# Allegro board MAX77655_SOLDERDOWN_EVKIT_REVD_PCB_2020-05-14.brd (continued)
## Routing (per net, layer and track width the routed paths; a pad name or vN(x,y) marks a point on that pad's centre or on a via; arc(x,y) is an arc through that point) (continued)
IN: length 89.5
  TOP w0.254: C5.2 30.85,23.66 v1(30.83,23.63)
  TOP w0.381: v1(1.71,64.93) SW2.1 2.85,63.75 3.67,62.94 R8.1 ; R37.1 8.74,46.1 8.72,46.08 2.48,46.08 2.44,46.12 v1(1.77,46.12)
  INTERNAL3 w0.254: v1(30.83,23.63) 28.74,23.63 24.9,27.47 6.6,27.47 5.31,28.76 5.31,28.95 IN_SNS.1
  INTERNAL3 w0.762: v1(1.71,64.93) 1.71,63.62 1.77,63.56 v1(1.77,46.12) 1.77,40.27 ; J5.1 1.96,40.46 1.77,40.27 ; IN.1 4.06,26.43 1.77,28.72 1.77,40.27
ISET_SBB0: length 12.6
  INTERNAL3 w0.254: v1(48.35,45.77) 48.35,46.52 48.35,46.53 v1(48.35,49.6)
  BOTTOM w0.254: U205.D2 42.98,46.42 43.64,45.76 47.73,45.76 47.74,45.77 v1(48.35,45.77) ; v1(48.35,49.6) 48.96,49.6 48.97,49.62 R203.1
ISET_SBB1: length 15.7
  INTERNAL3 w0.254: v1(46.25,36.93) 46.25,45.79 46.25,45.8 v1(46.25,46.41)
  BOTTOM w0.254: v1(46.25,46.41) 45.64,46.41 45.49,46.55 U205.D1 ; R224.1 48.91,37.19 48.65,36.93 v1(46.25,36.93)
ISET_SBB2: length 31.1
  INTERNAL3 w0.254: v1(46.87,23.23) 46.87,23.89 46.86,23.91 46.86,46.4 46.87,46.42 v1(46.87,47.03)
  BOTTOM w0.254: v1(46.87,23.23) 46.87,24.17 48.07,25.36 R237.1 ; v1(46.87,47.03) 46.23,47.03 46.2,47.06 U205.C1
ISET_SBB3: length 38.6
  INTERNAL3 w0.152: v1(44.2,47.72) 43.64,47.72 43.51,47.58 43.51,47.58 v2(43.15,47.23)
  INTERNAL3 w0.254: v1(47.6,47.71) v1(47.6,15.79)
  BOTTOM w0.152: U205.C2 42.98,47.06 v2(43.15,47.23)
  BOTTOM w0.254: v1(47.6,47.71) 46.72,47.71 46.71,47.72 v1(44.2,47.72) ; v1(47.6,15.79) R250.1
J3-5: length 20
  TOP w0.254: Q1.3 10.45,61.41 9.82,62.04 R8.2 7.43,62.04 v1(7.42,62.03)
  TOP w0.381: Q2.3 v1(7.42,65.72)
  INTERNAL3 w0.254: v1(7.42,65.72) 7.42,65.72 v1(7.42,62.03) 7.42,60.62 5.92,59.12 J3.5
LXB: length 2.2
  TOP w0.254: U1.C3 33.14,25.65 v2(32.99,25.49) ; U1.C3 v2(33.31,25.5) ; U1.C3 33,25.81 v2(33,25.82) ; U1.C3 33.31,25.8 33.31,25.8 33.32,25.81 v2(33.32,25.81)
  TOP w0.381: R34.1 34.8,22.06 v1(34.64,22.22)
  BOTTOM w0.152: 33.36,25.5 v2(33.31,25.5)
  BOTTOM w0.254: v2(32.99,25.49) 33.31,25.49 v2(33.31,25.5)
  BOTTOM w0.381: C4.2 33.71,25.46
  vias: v1(34.64,21.63)
NEN: length 119.5
  TOP w0.152: U1.C2 32.46,25.85 v2(32.46,25.86)
  TOP w0.203: v1(29.67,28.26) 25.66,32.27 v1(9.08,32.27)
  INTERNAL3 w0.203: v2(32.46,25.86) 32.07,25.86 v1(29.67,28.26)
  INTERNAL3 w0.254: J2.2 49.93,71.48 49.89,71.44 v1(49.89,69.64) ; v1(9.08,32.27) 9.08,32.88 9.1,32.89 v1(9.1,44.74) v1(9.1,68.77)
  BOTTOM w0.254: v1(49.89,69.64) 42.9,69.64 42.01,68.75 9.72,68.75 9.71,68.77 v1(9.1,68.77)
  BOTTOM w0.381: v1(9.1,44.74) 7.24,44.74 J3.2 J3.4 J3.6
NEN_EXT: length 9.7
  TOP w0.381: NEN_EXT.1 13.7,72.73 14.67,71.77 14.67,67.2 16.18,65.7 R33.1 16.19,64.91 R32.2
NEN_FTDI: length 38.1
  TOP w0.254: R31.1 11.13,63.12 11.13,63.12 v1(10.52,63.12)
  INTERNAL3 w0.254: v1(13.9,36.01) 13.9,40.03 11.38,42.55 11.38,62.26 v1(10.52,63.12)
  BOTTOM w0.254: U5.4 14.51,36.02 14.51,36.01 v1(13.9,36.01)
NIRQ: length 102.9
  TOP w0.152: U1.B2 32.49,26.32 v2(32.48,26.32)
  TOP w0.203: v1(29.56,29.25) 25.98,32.83 16.67,32.83 16.64,32.86 v1(16.06,32.86)
  TOP w0.254: NIRQ.1 15.38,39.28 15.39,39.29 v1(16.06,39.29) ; v1(16.67,65.97) v1(52.45,65.97)
  INTERNAL3 w0.152: v2(32.48,26.32) 32.48,26.33
  INTERNAL3 w0.203: v1(29.56,29.25) 32.18,26.63 32.19,26.63 32.48,26.33
  INTERNAL3 w0.254: v1(16.67,65.97) 16.67,61.65 16.06,61.04 v1(16.06,39.29) v1(16.06,32.86) ; J2.3 52.47,71.48 52.45,71.46 v1(52.45,65.97)
  BOTTOM w0.203: v1(16.06,32.86) 16.6,32.32
  BOTTOM w0.254: R27.2 R5.2 16.6,32.32
NIRQ_FTDI: length 2.2
  BOTTOM w0.254: U2.29 27.43,49.62 R19.1
RST#: length 2.5
  BOTTOM w0.254: R14.2 23.12,60.01 23.12,59.25 22.77,58.9 U2.14
SBB0: length 103.2
  TOP w0.203: v1(33.35,27.53) 33.45,27.63 33.45,27.96
  INTERNAL3 w0.203: B0_SNS.1 66.25,8.09 47.73,8.09 45.74,10.08 45.74,23.67 40.09,29.31 34.7,29.31 33.35,27.96 v1(33.35,27.53)
  INTERNAL3 w0.508: v1(33.58,30.68) 33.54,30.72 33.54,34.84 38.33,39.64 J4.4
  BOTTOM w0.508: B0_S.1 B0_SNS.1
  vias: v1(33.3,30.28)
SBB1: length 54.4
  TOP w0.203: U1.A4 33.85,26.84 33.85,27.02 34.46,27.63 34.46,27.66 v1(34.58,27.77) 34.7,27.89 35,27.89 35.05,27.93
  INTERNAL3 w0.203: v1(34.58,27.77) 34.99,28.18 37.26,28.18 37.56,28.49 39.04,28.49 44.56,22.98 44.56,9.31 46.81,7.05 61,7.05 B1_SNS.1
  BOTTOM w0.508: B1_S.1 B1_SNS.1
  vias: v1(38.3,27.83) v1(38.74,27.98)
SBB2: length 44.1
  INTERNAL3 w0.203: v1(34.6,26.64) 35.01,26.22 36.24,26.22 38.3,24.16 40.18,24.16 43.25,21.09 43.25,19.2 43.25,19.2 43.25,8.99 46.24,6 55.77,6 57.83,3.94 57.83,3.3 B2_SNS.1
  BOTTOM w0.508: B2_S.1 B2_SNS.1
  vias: v1(38.25,26.61) v1(38.68,26.33)
SBB3: length 36.6
  INTERNAL3 w0.203: v1(34.61,25.36) 35.19,25.36 37.51,23.04 39.26,23.04 42.13,20.18 42.13,8.25 45.41,4.97 49.91,4.97 B3_SNS.1
  BOTTOM w0.508: B3_S.1 B3_SNS.1
  vias: v1(38.34,25.52) v1(38.71,25.19)
SCL: length 96.6
  TOP w0.203: v1(26.51,33.04) 30.46,29.09 30.46,27.47 31.78,26.15 U1.B1
  TOP w0.254: J2.4 53.23,70.96 v1(44.74,70.96) ; SCL.1 11.57,34.42 12.96,34.42 13.14,34.25 25.31,34.25 v1(26.51,33.04)
  INTERNAL3 w0.254: v1(44.74,33.04) 44.74,47.38 44.75,47.39 44.75,47.77 44.74,47.78 v1(44.74,70.96)
  BOTTOM w0.203: R29.2 25.78,32.31 v1(26.51,33.04)
  BOTTOM w0.254: v1(26.51,33.04) v1(44.74,33.04)
SCL_FTDI: length 95.3
  TOP w0.254: v1(44.09,64.44) 44.09,64.29 43.68,63.89 v1(24.57,63.89)
  INTERNAL3 w0.203: v1(24.57,39.08) v1(24.57,57.68)
  INTERNAL3 w0.254: v1(24.57,63.89) 24.57,58.29 v1(24.57,57.68) ; v1(44.09,68.76) 44.09,68.08 44.09,68.08 v1(44.09,64.44) 44.09,63.83 44.11,63.81 44.11,55.03 39.67,50.58 39.67,50.4 v1(39.24,49.97)
  BOTTOM w0.203: v1(24.57,39.08) R22.2 24.01,38.15 23.48,37.62 U5.10 ; v1(24.57,57.68) 23.77,57.68 U2.16
  BOTTOM w0.254: v1(39.24,49.97) 39.05,49.97 38.75,49.66 R306.1 ; v1(44.09,68.76) 62,68.76 65.04,65.71 R304.1
  BOTTOM w0.381: R53.2 v1(44.09,64.44)
SDA: length 95.4
  TOP w0.203: U1.C1 31.55,25.65 v1(25.49,31.71) 19.8,31.71 19.76,31.67
  TOP w0.254: J2.5 55.15,70.33 46.13,70.33 v1(46.13,70.33) ; v1(19.77,31.7) 19.76,31.68 19.76,31.67 19.75,31.66 13.23,31.66 11.41,29.84 11.49,29.84 SDA.1
  INTERNAL3 w0.254: v1(45.53,32.99) 45.53,52.77 46.13,53.37 v1(46.13,70.33)
  BOTTOM w0.203: R30.2 19.77,32.28 19.77,31.82 19.77,31.82 v1(19.77,31.7)
  BOTTOM w0.254: v1(25.49,31.71) 26.1,31.71 26.75,32.36 44.9,32.36 v1(45.53,32.99)
SDA_FTDI: length 93.4
  TOP w0.254: 37.37,64.44 37.38,64.43 v1(37.38,64.42) ; 37.37,64.44 v1(42.84,64.44) ; 37.37,64.44 v1(25.83,64.44)
  INTERNAL3 w0.203: v1(25.82,56.05) v1(25.82,40.32)
  INTERNAL3 w0.254: v1(25.82,56.05) 25.82,56.66 25.83,56.67 v1(25.83,64.44) ; v1(42.84,64.44) 42.84,67.28 42.84,67.28 v1(42.84,67.95) ; v1(37.38,48.36) v1(37.38,64.42)
  BOTTOM w0.203: v1(25.82,40.32) 25.19,40.32 25.18,40.31 R21.2 ; U2.17 v1(25.82,56.05)
  BOTTOM w0.254: U2.18 U2.17 ; v1(42.84,67.95) 61.56,67.95 63.89,65.62 R303.1 ; U5.9 21.37,40.21 R21.2 ; R305.1 v1(37.38,48.36)
  BOTTOM w0.381: R54.2 v1(42.84,64.44)
UNNAMED_1_CAPNP_I203_2: length 0.8
  TOP w0.381: R34.2 36.31,21.16 C19.2
UNNAMED_1_CL-SB-12B-1X_I99_2: length 11.9
  TOP w0.254: v1(4.99,61.24) 5,61.25 SW2.2
  INTERNAL3 w0.254: v1(4.99,61.24) 4.99,56.84 4.68,56.53 4.68,52.38 J3.3
UNNAMED_1_DIOSCHOTTKY_I184_K: length 3.4
  BOTTOM w0.762: J5.2 6.73,43 6.74,43.01 D1.C
UNNAMED_1_EVQ-Q2XXXX_I7_3: length 12
  TOP w0.381: SW1.3 14.58,48.6 14.57,48.59 9.26,48.59 ; 9.26,48.59 J3.1 ; 9.26,48.59 9.43,48.42 R37.2
UNNAMED_1_RESSMD_I163_1: length 2
  TOP w0.254: R31.2 16.21,63.11 R3.1 16.22,62.05 R7.1
UNNAMED_1_RESSMD_I164_2: length 2.5
  TOP w0.254: R7.2 14.23,61.09 13.6,60.46 Q1.1
UNNAMED_1_RESSMD_I188_1: length 2.4
  TOP w0.381: Q2.1 13.62,64.77 14.36,64.04 R32.1
UNNAMED_2_CAPNP_I56_2: length 7.8
  BOTTOM w0.254: U210.3 U210.4
  BOTTOM w0.381: R277.2 78.35,56.11 78.47,56 U210.4 80.8,55.12 80.78,55.1 C234.2
UNNAMED_2_CAPNP_I61_2: length 5.9
  BOTTOM w0.381: U210.6 80.8,58.67 80.78,58.68 C235.2 ; U210.6 U210.5 ; U210.6 78.41,57.9 78.28,57.76 R279.1
UNNAMED_2_CAPNP_I79_2: length 5.1
  BOTTOM w0.381: 70.99,66.28 70.99,66.69 R281.2 ; 70.99,66.28 71.81,66.28 R282.1 72.28,66.75 C238.2 ; 70.99,66.28 U209.12
UNNAMED_2_CAPNP_I84_2: length 4.9
  BOTTOM w0.381: U209.6 70.36,57.29 70.3,57.24 70.3,56.39 70.29,56.38 C252.2 70.29,54.88 R301.1 R302.2
UNNAMED_2_CAPNP_I95_2: length 6.1
  BOTTOM w0.381: U209.5 70.99,57.56 71.92,56.63 72.59,56.63 72.97,56.25 C7.2 72.97,54.89 R4.1 72.95,54.05 R1.2
UNNAMED_2_CAPNP_I101_2: length 4.4
  BOTTOM w0.381: C9.2 68.97,66.89 R6.1 68.99,66.91 69.83,66.91 R2.2 69.84,66.46 70.35,65.95 U209.11
UNNAMED_2_EKRESSMD_I66_2: length 3
  BOTTOM w0.381: U209.16 74.48,64.48 74.5,64.5 C237.2 75.2,65.21 75.2,65.22 R286.2
UNNAMED_2_EKRESSMD_I73_2: length 11.5
  BOTTOM w0.381: R303.2 63.89,62.11 64.34,61.65 71.42,61.65 72.26,62.49 U209.14
UNNAMED_2_EKRESSMD_I74_2: length 8.1
  BOTTOM w0.381: U209.13 71.62,63.16 71.22,62.75 R304.2
UNNAMED_2_EKRESSMD_I91_1: length 21
  INTERNAL3 w0.381: AIN1.1 69.84,72.16 69.77,72.09 69.77,54.56 v1(71.2,53.12)
  BOTTOM w0.381: R302.1 v1(71.2,53.12)
UNNAMED_2_EKRESSMD_I96_1: length 28.8
  INTERNAL3 w0.381: v1(65.59,52.11) 65.59,72.19 AIN0.1
  BOTTOM w0.381: v1(65.59,52.11) 71.27,52.11 72.06,52.9 R1.1
UNNAMED_2_RESSMD_I67_2: length 6.1
  BOTTOM w0.381: R288.2 77.14,66.48 Q205.1 78.99,65.71 78.99,65.7 Q206.3
UNNAMED_2_RESSMD_I82_1: length 10.7
  BOTTOM w0.381: AIN7.1 79.03,72.73 75.94,69.65 71.94,69.65 70.76,68.47 R281.1
UNNAMED_2_RESSMD_I99_1: length 7.5
  BOTTOM w0.381: AIN6.1 72.99,72.73 69.84,69.58 R2.1
UNNAMED_4_AT24CS02_I136_SCL: length 2.4
  BOTTOM w0.381: R53.1 44.09,62.48 44.12,62.45 U7.6
UNNAMED_4_AT24CS02_I136_SDA: length 2.4
  BOTTOM w0.381: U7.5 42.85,62.47 42.84,62.48 R54.1
UNNAMED_4_AT24CS02_I136_VCC: length 4.4
  BOTTOM w0.381: R20.2 46.62,62.5 46.66,62.46 U7.8 47.75,60.72 47.76,60.73 47.94,60.73 C73.2
UNNAMED_4_AT24CS02_I136_WP: length 2.4
  BOTTOM w0.381: U7.7 45.39,62.48 45.4,62.49 R52.2
UNNAMED_4_FT2232H_I13_ACBUS4: length 23.7
  INTERNAL3 w0.203: v1(29.85,48.99) v1(29.85,42.52)
  BOTTOM w0.203: v1(29.85,42.52) 29.17,42.52 29.16,42.51 21.08,42.51 19.77,41.2 U5.7 ; v1(29.85,48.99) 29.72,49.12 U2.30
UNNAMED_4_LED_I121_B: length 1.7
  TOP w0.381: R28.1 37.9,49.33 DS2.K
UNNAMED_4_LED_I128_B: length 1.6
  TOP w0.381: DS1.K 30.85,51.1 v1(30.18,51.1)
  BOTTOM w0.381: R18.1 v1(30.18,51.1)
UNNAMED_4_MAX3395E_I143_I: length 24
  INTERNAL3 w0.254: v1(31.38,42) v1(31.38,49.47)
  BOTTOM w0.254: R18.2 30.24,49.54 30.39,49.54 ; 30.39,49.54 30.32,49.62 R19.2 ; 30.39,49.54 30.46,49.47 v1(31.38,49.47) ; U5.8 20.57,41.34 21.23,42 v1(31.38,42)
UNNAMED_4_MAX3395E_I143_I_1: length 2.6
  BOTTOM w0.203: R29.1 R26.2 21.59,33.77 21.37,33.99 U5.1
UNNAMED_4_MAX3395E_I143_I_2: length 2.7
  BOTTOM w0.203: U5.2 20.57,33.91 20.71,33.77 R25.2 R30.1
UNNAMED_4_MAX3395E_I143_I_3: length 2.1
  BOTTOM w0.203: U5.3 19.77,34.54 18.87,33.64 R27.1
UNNAMED_4_MAX8512_I103_FB: length 3
  BOTTOM w0.381: U3.4 33.91,60.77 33.69,60.99 R16.2 32.97,59.93 R17.1
UNNAMED_4_MAX8512_I112_FB: length 3
  BOTTOM w0.381: U4.4 34.17,52.99 33.84,53.33 33.15,53.33 R23.2 32.27,53.32 32.25,53.31 R24.1
UNNAMED_6_CAPNP_I21_1: length 18.7
  BOTTOM w0.254: R205.1 62.89,47.86 C203.1 61.86,47.84 61.24,47.84 61,48.09 U200.7
  BOTTOM w0.381: R202.2 50.04,48.78 49.66,48.4 49.66,46.12 50.26,45.52 55.62,45.52 58.13,48.04 58.47,48.04 58.52,48.09 U200.7
UNNAMED_6_CAPNP_I21_2: length 9.9
  BOTTOM w0.254: R208.1 63.51,49.53 63.32,49.34 62.48,49.34 62.48,49.34 62.01,49.34 ; C203.2 61.87,49.17 62.01,49.3 62.01,49.34 ; C203.2 61.88,48.76 R205.2 ; C203.2 61.24,48.76 61.22,48.74 U200.6 ; 62.01,49.34 61.85,49.49 R294.2
UNNAMED_6_CAPNP_I22_2: length 11.5
  BOTTOM w0.254: C204.2 60.74,51.06 61.09,50.71 61.82,50.71 R293.1 61.86,51.33 62.06,51.53 64.23,51.53 65.28,50.48 66.83,50.48 66.84,50.47 R207.1 ; C204.2 59.77,50.43 59.76,50.42 U200.5 ; C204.2 59.77,51.98 R206.2
UNNAMED_6_CAPNP_I271_2: length 15.8
  BOTTOM w0.254: R229.1 68.66,37.99 68.54,38.12 66.94,38.12 66.46,38.59 63.07,38.59 62.15,39.51 60.41,39.51 60.23,39.33 R295.1 59.65,38.73 59.63,38.74 C208.2 ; C208.2 57.86,39.82 R226.2 ; C208.2 57.86,38.11 57.86,38.11 U201.5
UNNAMED_6_CAPNP_I277_1: length 18.5
  BOTTOM w0.254: U201.7 59.49,35.45 59.56,35.51 R228.1 61.32,35.51 C209.1
  BOTTOM w0.381: R223.2 48.68,36.28 48.27,35.86 48.27,33.15 48.65,32.77 53.67,32.77 56.37,35.47 57.84,35.47 U201.7
UNNAMED_6_CAPNP_I277_2: length 14.1
  BOTTOM w0.254: R228.2 60.21,36.43 C209.2 61.86,36.43 63.51,38.07 66.03,38.07 67.08,37.03 R230.1 ; R228.2 60.19,36.99 60.2,37.01 R296.2 ; R228.2 59.56,36.41 59.24,36.1 U201.6
UNNAMED_6_CAPNP_I289_2: length 4.1
  BOTTOM w0.254: U201.3 51.98,36.1 50.89,37.19 R224.2 C248.2
UNNAMED_6_CAPNP_I307_2: length 17.2
  BOTTOM w0.254: U202.5 57.78,25.76 57.77,25.77 57.77,26.08 57.75,26.1 C214.2 ; R242.1 67.88,27.68 65.54,25.34 64.02,25.34 61.45,27.91 60.51,27.91 60.15,27.55 R297.1 58.81,27.21 58.33,26.73 C214.2 ; C214.2 57.77,26.74 57.77,27.46 57.75,27.48 R240.2
UNNAMED_6_CAPNP_I311_1: length 19
  BOTTOM w0.254: R239.1 C213.1 59.41,23.78 59.15,23.53 U202.7
  BOTTOM w0.381: U202.7 56.53,23.53 56.52,23.52 56.06,23.52 52.7,20.17 49.35,20.17 48.26,21.26 48.26,24.2 48.53,24.47 R236.2
UNNAMED_6_CAPNP_I311_2: length 14.1
  BOTTOM w0.254: R298.2 60.1,25.32 60.04,25.27 C213.2 ; R243.1 67.77,26.85 65.51,24.6 61.96,24.6 61.87,24.68 R239.2 C213.2 ; C213.2 59.46,24.68 58.96,24.18 U202.6
UNNAMED_6_CAPNP_I323_2: length 4.2
  BOTTOM w0.254: U202.3 51.89,24.18 50.71,25.36 R237.2 C250.2
UNNAMED_6_CAPNP_I341_2: length 16.6
  BOTTOM w0.254: R252.2 57.86,18.67 C218.2 57.86,17.14 57.88,17.12 U203.5 59.06,15.41 59.44,15.79 R299.1 60.09,16.42 61.41,17.75 65.64,17.75 67.16,19.26 R254.1
UNNAMED_6_CAPNP_I345_1: length 19.2
  BOTTOM w0.254: R253.1 60.15,13.17 C219.1 59.92,13.17 59.77,13.33 59.77,13.59 59.24,14.11 U203.7
  BOTTOM w0.381: R249.2 48.77,14.86 47.89,13.98 47.89,11.75 48.38,11.26 53.2,11.26 56.05,14.11 56.63,14.11 56.63,14.11 U203.7
UNNAMED_6_CAPNP_I345_2: length 14
  BOTTOM w0.254: U203.6 59.08,14.76 59.26,14.94 R300.2 60.14,14.87 C219.2 61.06,14.07 R253.2 61.1,14.11 61.71,14.11 64.79,17.19 65.83,17.19 67.06,18.43 R255.1
UNNAMED_6_CAPNP_I357_2: length 4.2
  BOTTOM w0.254: U203.3 51.9,14.76 50.88,15.79 R250.2 50.31,16.65 C251.2
UNNAMED_6_CAPNP_I359_2: length 4.1
  BOTTOM w0.254: C200.2 52.22,50.46 R203.2 52.24,49.64 52.95,49.64 53.85,48.74 U200.3
UNNAMED_6_EKCAPNP_I10_1: length 3.7
  BOTTOM w0.254: U200.2 52.92,48.09 52.82,47.99 C201.1 52.24,48.77 R202.1
UNNAMED_6_EKCAPNP_I10_2: length 0.8
  BOTTOM w0.381: R201.1 51.35,47.98 C201.2
UNNAMED_6_EKCAPNP_I203_2: length 1.4
  BOTTOM w0.254: U205.D3 42.48,45.94 42.69,45.73 C223.2
UNNAMED_6_EKCAPNP_I237_2:
  vias: v1(77.95,47.48) v1(77.97,49.17) v1(77.97,45.13) v1(79.82,49.21) v1(79.8,47.52) v1(79.8,45.11) v1(80.01,42.62) v1(81.75,47.54) v1(81.72,45.13) v1(81.7,42.62) v1(81.77,49.24) v1(82.94,49.24) v1(82.92,47.54) v1(84.2,49.25) v1(84.2,47.56) v1(84.22,45.11) v1(84.2,42.6) v1(85.62,42.6) v1(86.18,49.25) v1(86.16,47.25) v1(86.6,45.03) v1(88.73,42.65) v1(88.82,49.6) v1(88.78,47.29) v1(88.75,45.03) v1(90.9,47.29) v1(90.88,45.03) v1(90.86,42.65)
UNNAMED_6_EKCAPNP_I261_2:
  vias: v1(78.3,36.36) v1(78.26,34.52) v1(78.26,33.14) v1(79.79,36.39) v1(79.81,34.52) v1(79.84,33.05) v1(79.75,31.24) v1(81.72,36.39) v1(81.71,34.49) v1(81.74,31.21) v1(82.92,36.41) v1(82.91,34.52) v1(83.58,31.21) v1(84.24,36.41) v1(84.28,34.49) v1(85.88,36.41) v1(85.86,34.49) v1(85.92,33.11) v1(86.01,31.21) v1(88.32,33.05) v1(88.38,31.27) v1(90.51,35.98) v1(90.57,31.24)
UNNAMED_6_EKCAPNP_I287_1: length 3.6
  BOTTOM w0.254: U201.2 50.99,35.45 50.97,35.43 C206.1 R223.1
UNNAMED_6_EKCAPNP_I287_2: length 0.9
  BOTTOM w0.254: R222.1 C206.2
UNNAMED_6_EKCAPNP_I298_2:
  vias: v1(78.11,25.33) v1(79.75,25.27) v1(79.81,22.93) v1(79.87,21.18) v1(81.3,25.25) v1(81.39,24.02) v1(81.42,21.18) v1(82.85,25.25) v1(82.91,23.99) v1(82.94,21.21) v1(84.43,21.27) v1(84.55,24) v1(86.27,26.5) v1(86.3,21.3) v1(88.35,26.47) v1(88.38,25.21) v1(88.41,23.55) v1(90.37,26.5) v1(90.4,25.16) v1(90.4,23.55) v1(90.4,21.41)
UNNAMED_6_EKCAPNP_I321_1: length 3.8
  BOTTOM w0.254: U202.2 50.82,23.53 50.76,23.59 C211.1
  BOTTOM w0.381: C211.1 50.17,23.59 R236.1
UNNAMED_6_EKCAPNP_I321_2: length 0.9
  BOTTOM w0.254: C211.2 R235.1
UNNAMED_6_EKCAPNP_I332_2:
  vias: v1(78.11,15.21) v1(78.14,13.93) v1(79.9,15.21) v1(79.95,13.87) v1(79.98,12.03) v1(80.02,10.24) v1(81.56,15.27) v1(81.56,13.9) v1(81.56,10.24) v1(82.7,14.6) v1(82.67,12.93) v1(82.79,10.24) v1(85.92,10.24) v1(85.95,15.36) v1(85.95,13.49) v1(85.95,11.94) v1(88.23,15.36) v1(88.2,13.49) v1(88.26,11.97) v1(88.26,10.27) v1(90.54,15.37) v1(90.51,13.5) v1(90.48,11.97) v1(90.51,10.21)
UNNAMED_6_EKCAPNP_I355_1: length 3.8
  BOTTOM w0.254: U203.2 51.01,14.11 50.89,13.98 C216.1 50.31,14.85 R249.1
UNNAMED_6_EKCAPNP_I355_2: length 0.9
  BOTTOM w0.254: R248.1 C216.2
UNNAMED_6_EKCAPNP_I377_1: length 1.7
  BOTTOM w0.381: U211.3 55.12,63.26 55.12,64.01 55.12,64.01 C270.1
UNNAMED_6_EKCAPNP_I377_2: length 5
  BOTTOM w0.381: U211.6 56.99,61.32 56.7,61.61 56.7,64.17 56.02,64.84 C270.2
UNNAMED_6_EKCAPNP_I423_2: length 2.9
  BOTTOM w0.381: U211.5 59.28,62.27 59.29,62.28 C273.2 60.01,62.25 R289.2
UNNAMED_6_EKRESSMD_I42_2: length 28.2
  INTERNAL3 w0.381: v1(75.42,52.98) 76.45,52.98 78.28,51.15 86.87,51.15 87.34,50.68 89.5,50.68 91.48,48.7 VIL_SBB0.1
  BOTTOM w0.254: R207.2 70.98,50.47 72.11,51.6 75.19,51.6 75.4,51.81 R211.1
  BOTTOM w0.381: R211.1 75.4,52.96 v1(75.42,52.98)
UNNAMED_6_EKRESSMD_I99_1: length 3.7
  BOTTOM w0.254: R204.1 52.25,46.41 R201.2 52.83,47.22 53.05,47.44 U200.1
UNNAMED_6_EKRESSMD_I99_2: length 52.9
  TOP w0.381: v1(50.49,55.86) 51.19,55.86 51.2,55.85 J200.2
  INTERNAL3 w0.381: v1(50.49,46.42) v1(50.49,55.86)
  BOTTOM w0.381: v1(50.49,46.42) 51.35,46.42 R204.2
UNNAMED_6_EKRESSMD_I207_2: length 2.5
  INTERNAL3 w0.254: v1(40.12,47.39) 40.29,47.23 v2(41.8,47.23)
  BOTTOM w0.152: U205.C4 41.97,47.06 v2(41.8,47.23)
  BOTTOM w0.254: v1(40.12,47.39) 40.1,47.37 R214.2
UNNAMED_6_EKRESSMD_I222_2: length 1.9
  BOTTOM w0.254: R283.2 40.24,46.46 40.34,46.55 U205.D5
UNNAMED_6_EKRESSMD_I273_2: length 26.3
  INTERNAL3 w0.381: VIL_SBB1.1 90.82,34.49 86.82,38.48 76.06,38.48 v1(75.04,39.49)
  BOTTOM w0.254: R233.1 75.01,38.25 74.75,37.99 R229.2
  BOTTOM w0.381: R233.1 v1(75.04,39.49)
UNNAMED_6_EKRESSMD_I278_1: length 3.9
  BOTTOM w0.254: R225.1 R222.2 50.97,34.49 51.28,34.8 U201.1
UNNAMED_6_EKRESSMD_I278_2: length 58.4
  TOP w0.381: v1(48.88,44.42) v1(76.11,44.42)
  INTERNAL3 w0.381: v1(76.11,44.42) 84.81,44.42 91.45,37.78 J202.1 ; v1(49.01,33.51) 48.88,33.64 v1(48.88,44.42)
  BOTTOM w0.381: R225.2 v1(49.01,33.51)
UNNAMED_6_EKRESSMD_I306_2: length 28.5
  INTERNAL3 w0.381: VIL_SBB2.1 91.61,19.23 84.15,26.69 77.21,26.69 v1(74.98,28.92)
  BOTTOM w0.254: R242.2 70.64,27.68 70.79,27.53 74.76,27.53 75.01,27.78 R245.1
  BOTTOM w0.381: R245.1 v1(74.98,28.92)
UNNAMED_6_EKRESSMD_I313_1: length 3.9
  BOTTOM w0.254: R238.1 R235.2 50.76,22.74 50.9,22.88 U202.1
UNNAMED_6_EKRESSMD_I313_2: length 70.5
  INTERNAL3 w0.381: v1(50.3,9.16) 50.27,9.18 v1(50.27,20.8) ; v1(89.33,19.38) 89.33,9.62 89.34,9.61 v1(89.34,8.86)
  BOTTOM w0.254: R238.2 49.28,21.14 49.61,20.8 v1(50.27,20.8)
  BOTTOM w0.381: J204.1 93.14,21.57 90.95,19.38 v1(89.33,19.38) ; v1(89.34,8.86) 51.27,8.86 50.97,9.16 v1(50.3,9.16)
UNNAMED_6_EKRESSMD_I340_2: length 31.9
  INTERNAL3 w0.381: VIL_SBB3.1 84.88,4.7 84.88,15.11 82.96,17.03 77.1,17.03 76.39,17.74 75.47,17.74 v1(74.99,18.22)
  BOTTOM w0.254: R254.2 70.64,19.26 73.17,16.73 74.66,16.73 75.01,17.08 R258.1
  BOTTOM w0.381: R258.1 v1(74.99,18.22)
UNNAMED_6_EKRESSMD_I347_1: length 3.9
  BOTTOM w0.254: R251.1 50.31,12.25 R248.2 50.89,13.1 51.25,13.46 U203.1
UNNAMED_6_EKRESSMD_I347_2: length 48.8
  TOP w0.381: v1(48.77,9.18) 49.78,8.18 90.21,8.18 90.76,7.62 J206.1
  INTERNAL3 w0.381: v1(48.77,12.24) v1(48.77,9.18)
  BOTTOM w0.381: R251.2 v1(48.77,12.24)
UNNAMED_6_EKRESSMD_I450_2: length 2.7
  INTERNAL3 w0.254: v1(40.09,48.35) 40.2,48.35 40.82,47.74 v2(41.79,47.74)
  BOTTOM w0.152: v2(41.79,47.74) 41.97,47.55 U205.B4
  BOTTOM w0.254: R305.2 40.08,48.36 v1(40.09,48.35)
UNNAMED_6_EKRESSMD_I451_2: length 3.1
  BOTTOM w0.254: R306.2 40.23,49.24 40.24,49.22 40.27,49.22 40.66,48.84 40.66,47.84 40.95,47.55 U205.B5
UNNAMED_6_HEADER2P_I442_1: length 8.5
  BOTTOM w0.381: Q200.4 86.24,52.58 86.29,52.64 86.45,52.64 86.46,52.65 R210.1 87.93,52.65 87.94,52.64 91.07,52.64 91.74,53.31 J200.1
UNNAMED_6_HEADER2P_I444_2: length 8.8
  BOTTOM w0.381: Q201.4 86.33,38.79 86.33,38.79 R231.1 88.77,38.79 90.31,40.34 91.72,40.34 91.74,40.32 J202.2
UNNAMED_6_HEADER2P_I446_2: length 9
  BOTTOM w0.381: Q202.4 85.91,28.66 86.36,28.21 R244.1 91.66,28.21 J204.2
UNNAMED_6_HEADER2P_I448_2: length 14.3
  INTERNAL3 w0.381: v1(91.57,17.25) 91.57,11.86 J206.2
  BOTTOM w0.381: v1(91.57,17.25) 91.1,17.72 89.17,17.72 89.16,17.71 87.85,17.71 87.83,17.69 R257.1 86.01,17.69 86,17.71 Q203.4
USB_DM: length 3.1
  TOP w0.203: R10.1 21.16,70.3 21.26,70.4 21.26,72.1 J1.2
USB_DP: length 3.2
  TOP w0.203: J1.3 20.61,72.1 20.61,70.68 20.23,70.31 R11.1
VADC: length 19.1
  INTERNAL3 w0.254: v1(76.22,54.99) v1(76.22,67.88)
  BOTTOM w0.254: 75.99,67.83 76.03,67.88 v1(76.22,67.88) ; R277.1 v1(76.22,54.99)
  BOTTOM w0.381: R286.1 75.2,67.43 75.59,67.82 75.98,67.82 75.99,67.83 R288.1 76.73,67.83 77.27,68.38 Q205.2
VLOGIC: length 88.4
  TOP w0.381: v1(17,33.53) v1(23.99,33.53) ; J4.5 J4.3 J4.1 42.19,72.89 42.35,72.73 J2.1
  TOP w0.508: v1(33.13,36.18) 25.08,36.18 24.76,35.86 v1(24.02,35.86)
  INTERNAL3 w0.381: v1(24,31.15) 24,33.5 ; 24,33.5 24,35.17 24.02,35.19 v1(24.02,35.86) 22.27,37.62 v1(17.16,37.62) ; 24,33.5 23.99,33.51 v1(23.99,33.53)
  INTERNAL3 w0.508: J4.5 33.96,71.06 33.96,53.01 33.36,52.41 33.36,36.41 v1(33.13,36.18)
  BOTTOM w0.203: U5.12 23.86,36.02 24.03,35.84 C44.2 ; R25.1 20.71,32.31 R26.1
  BOTTOM w0.254: U5.6 v1(17.16,37.62) ; R5.1 17.32,33.22 v1(17,33.53) ; v1(24.02,35.86) 24.57,35.86 C44.2
  BOTTOM w0.381: v1(24,31.15) 21.21,31.15 20.71,31.66 R25.1
VPHY: length 4.5
  BOTTOM w0.254: U2.4 17.77,59.33 17.76,59.33 C26.2 17.76,60.83 17.37,61.22 L5.2
VPLL: length 4.5
  BOTTOM w0.254: U2.9 20.27,59.13 20.37,59.24 C27.2 20.37,60.98 20.61,61.22 20.61,61.96 L4.2
VREGOUT: length 3.3
  BOTTOM w0.254: U2.49 12.98,48.12 12.78,47.92 C28.2 12.01,46.91 R15.2
VUSB: length 213.8
  TOP w0.508: v1(58.65,66.76) 80.69,66.76 v1(81.14,66.31) ; 24.83,68.91 26.2,68.91 VUSB.1
  INTERNAL3 w0.381: v1(59.77,21.03) 59.77,20.87 59.76,20.86 ; v1(59.71,33.22) 59.71,33.23 59.76,33.27
  INTERNAL3 w0.508: v1(59.76,11.77) v1(59.76,46.27) 59.76,57.87 58.65,58.98 v1(58.65,66.76)
  INTERNAL3 w0.635: v1(40.37,52.78) v1(40.37,60.65) v1(40.37,66.95)
  INTERNAL3 w0.762: v1(8.33,66.83) 8.33,59.92 7.79,59.39 7.79,37.88 v1(7.75,37.84)
  BOTTOM w0.254: C207.1 57.81,33.85 57.86,33.9 U201.8 ; U200.8 59.76,46.53 59.76,46.53 v1(59.76,46.27) ; C217.1 57.9,12.36 57.88,12.38 U203.8 ; U202.8 57.78,21.98 57.8,21.96 57.8,21.67 57.81,21.66 C212.1
  BOTTOM w0.381: C212.1 v1(59.77,21.03) ; R287.1 83.07,63.49 82.67,63.89 81.22,63.89 Q206.1 81.19,65.26 81.19,65.27 Q205.3 ; C217.1 58.54,11.73 58.58,11.77 v1(59.76,11.77) ; C202.1 v1(59.76,46.27) ; U3.1 36.25,62.07 36.2,62.02 36.18,62.02 35.92,61.76 35.92,61.04 36.19,60.77 U3.3 38.41,60.77 38.55,60.63 C29.2 ; v1(40.37,52.78) C41.2 38.6,52.78 38.39,52.99 U4.3 36.32,52.99 36.25,53.06 36.25,54.03 36.52,54.29 U4.1 ; C207.1 v1(59.71,33.22)
  BOTTOM w0.508: 81.19,65.9 81.14,65.95 v1(81.14,66.31)
  BOTTOM w0.635: C29.2 39.3,60.65 v1(40.37,60.65) ; v1(58.65,66.76) 57.85,66.76 57.65,66.95 v1(40.37,66.95) 25.87,66.95 25.87,66.95 v1(25.07,66.95)
  BOTTOM w0.762: v1(8.33,66.83) 24.09,66.83 v1(24.21,66.95) v1(25.07,66.95) ; v1(7.75,37.84) 7.83,37.92 D1.A

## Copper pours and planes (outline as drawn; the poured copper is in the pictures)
PVDD on TOP: 35.31,23.72 34.8,23.72 34.8,24.26 34.42,24.26 33.53,25.02 33.53,25.27 33.78,25.27 34.42,24.77 35.18,24.77 35.31,24.64
VDD on TOP: 32.13,27.18 32.51,26.8 32.77,26.8 32.77,28.7 32.51,28.96 32.38,29.21 32.13,29.21
GROUND on TOP: 16.51,73.03 16.51,70.61 19.56,70.61 19.56,73.03
GROUND on TOP: 52.58,13.46 66.31,13.46 66.33,13.44 67.16,12.61 67.16,8.16 67.19,8.13 52.58,8.13 51.94,8.76 51.94,12.83
GROUND on TOP: 52.32,18.67 51.05,19.94 51.05,21.08 51.69,21.72 67.1,21.72 67.08,21.7 70.76,21.7 71.63,20.83 75.82,20.83 76.83,19.81 76.83,13.46 76.33,13.46 76.33,13.97 71.63,18.67
GROUND on TOP: 64.64,29.59 76.45,29.59 76.58,29.46 76.58,24.51 76.2,24.51 74.8,25.91 53.98,25.91 52.83,27.05 52.83,27.43 53.21,27.81 62.87,27.81
GROUND on TOP: 0.76,19.05 0.76,8.13 30.35,8.13 32.13,6.48 32.13,0.76 37.97,0.76 37.97,18.67 9.4,18.67 9.02,19.05
GROUND on TOP: 22.99,73.03 22.99,70.61 26.29,70.61 26.29,73.03
GROUND on TOP: 52.83,34.04 52.83,36.96 62.74,36.96 63.25,37.47 67.12,37.47 67.1,37.45 75.46,37.45 76.45,36.45 76.45,33.78 75.69,33.78 75.44,34.04
GROUND on TOP: 31.11,28.83 31.11,27.3 31.75,26.67 32.13,26.67 32.13,26.92 31.75,27.3 31.75,28.83
GROUND on TOP: 37.97,31.75 39.5,31.75 39.5,30.73 37.08,28.32 37.08,23.5 39.24,21.34 39.24,19.94 37.26,19.94 37.2,20.01 36.69,20.51 36.69,20.94 35.31,22.61 35.18,22.73 33.27,22.73 32.77,23.24 32.77,24.13 33.02,24.38 33.02,25.27 33.27,25.27 33.27,25.02 33.4,24.77 33.78,24.51 34.04,24.51 34.42,24.13 34.42,23.75 34.54,23.62 35.43,23.62 35.56,23.75 35.56,24.64 35.94,25.02 35.94,28.45 35.69,28.68 33.2,28.68 32.94,28.93 32.94,29.59 33.05,29.69 35.92,29.69
GROUND on BOTTOM: 0.74,75.8 94.74,75.69 94.74,15.11 94.22,15.88 93.34,16.18 91.9,14.73 93.34,13.28 94.22,13.58 94.74,14.35 94.74,1.27 88.11,1.23 88.52,1.76 88.67,2.41 87.12,3.96 85.58,2.41 85.73,1.75 86.15,1.22 74.55,1.14 74.55,8.13 74.42,8.26 44.7,8.26 43.81,7.37 43.81,1.14 0.89,1.14 ; 34 cut-outs
GROUND on INTERNAL2: 1.4,75.56 88.27,75.56 94.61,69.22 94.61,6.22 89.53,1.14 74.55,1.14 74.55,8.13 73.91,8.76 45.21,8.76 43.81,7.37 43.81,1.14 1.4,1.14 ; 6 cut-outs
IN on TOP: 32.26,25.3 31.24,25.3 28.7,27.81 0.76,27.81 0.76,19.43 27.43,19.43 30.99,22.99 31.88,22.99 32.13,23.24 32.13,24.77 32.38,25.05 32.38,25.17
LXA on TOP: 32.51,25.27 32.77,25.27 32.77,19.18 31.11,19.18 31.11,22.73 31.24,22.86 32,22.86 32.26,23.11 32.26,24.64 32.51,24.89
LXB on TOP: 34.92,22.61 35.05,22.48 35.05,19.18 33.53,19.18 33.53,22.61
LXB on INTERNAL3: 32.77,21.97 33.38,21.34 34.89,21.34 35.05,21.34 35.05,22.35 33.66,23.75 33.66,25.91 33.53,26.04 32.89,26.04 32.77,25.91
SBB0 on TOP: 33.07,26.55 33.07,28.38 33.88,28.38 33.88,27.47 33.27,26.86 33.27,26.55
SBB0 on TOP: 58.8,38.35 57.66,37.21 42.93,37.21 35.69,29.97 33.02,29.97 33.02,33.15 40.72,40.77 43.81,43.94 75.95,43.94 75.95,40.51 73.79,38.35
SBB0 on BOTTOM: 33.64,27.24 33.08,27.24 33.08,30.85 33.33,31.1 33.79,31.1 34.07,30.87 34.07,27.7
SBB1 on TOP: 33.56,26.53 33.56,26.84 34.32,27.6 34.32,28.36 35.44,28.36 35.44,27.29 35.38,27.24 34.52,27.24 33.81,26.53
SBB1 on TOP: 37.47,28.45 37.47,27.3 52.2,27.3 52.96,28.07 62.36,28.07 64.14,29.84 76.07,29.84 76.07,32.77 75.06,33.78 62.1,33.78 60.96,32.64 41.66,32.64
SBB1 on BOTTOM: 34.3,28.41 39.4,28.41 39.4,27.4 34.3,27.4
SBB2 on TOP: 37.47,27.05 51.56,27.05 52.96,25.65 74.68,25.65 76.07,24.26 76.07,21.08 71.75,21.08 70.87,21.97 49.78,21.97 48.13,23.62 43.05,23.62 40.64,26.04 37.47,26.04
SBB2 on TOP: 35.44,26.15 34.12,26.15 34.02,26.05 33.56,26.05 33.56,26.2 33.61,26.25 33.77,26.25 34.58,27.06 35.39,27.06 35.44,27.01
SBB2 on BOTTOM: 34.3,26.97 39.38,26.97 39.38,25.96 34.3,25.96
SBB3 on TOP: 70.61,18.29 52.2,18.29 47.88,22.61 43.31,22.61 40.13,25.78 37.47,25.78 37.47,23.5 46.99,13.97 67.26,13.97 70.3,10.92 76.06,10.92 76.06,13.73 75.82,13.97 75.82,13.97 71.5,18.29
SBB3 on TOP: 35.38,24.92 34.42,24.92 33.53,25.65 33.66,25.78 33.81,25.83 35.38,25.83
SBB3 on BOTTOM: 34.29,25.77 39.37,25.77 39.37,24.88 34.29,24.88
UNNAMED_6_EKCAPNP_I237_2 on TOP, BOTTOM: 76.71,41.4 91.69,41.4 91.69,50.55 76.71,50.55
UNNAMED_6_EKCAPNP_I261_2 on TOP: 76.96,38.1 91.44,38.1 91.44,28.83 76.96,28.83
UNNAMED_6_EKCAPNP_I261_2 on BOTTOM: 76.96,30.48 91.44,30.48 91.44,37.34 76.96,37.34
UNNAMED_6_EKCAPNP_I298_2 on TOP: 76.96,17.91 91.44,17.91 91.44,28.19 76.96,28.19
UNNAMED_6_EKCAPNP_I298_2 on BOTTOM: 76.96,20.07 91.44,20.07 91.44,27.05 76.96,27.05
UNNAMED_6_EKCAPNP_I332_2 on TOP: 77.22,8.26 91.44,8.26 91.44,17.27 77.22,17.27
UNNAMED_6_EKCAPNP_I332_2 on BOTTOM: 77.22,16.26 77.22,9.91 91.44,9.91 91.44,16.26
UNNAMED_6_EKRESSMD_I42_2 on BOTTOM: 79.25,53.59 78.49,54.36 74.68,54.36 74.68,52.32 77.22,52.32 78.23,51.31 79.32,51.29 84.07,51.31 84.07,53.59
UNNAMED_6_EKRESSMD_I273_2 on BOTTOM: 78.87,40.14 78.11,40.9 74.3,40.9 74.3,38.87 76.83,38.87 77.85,37.85 78.94,37.84 83.69,37.85 83.69,40.14
UNNAMED_6_EKRESSMD_I306_2 on BOTTOM: 74.17,28.45 79.5,28.45 80.01,27.94 84.07,27.94 84.07,30.23 74.17,30.23
UNNAMED_6_EKRESSMD_I340_2 on BOTTOM: 74.17,17.78 75.95,17.78 76.96,16.76 84.33,16.76 84.33,19.81 74.42,19.81 74.17,19.56
VUSB on TOP: 23.5,70.1 23.5,66.55 25.4,66.55 25.65,66.8 25.65,70.1

Small or netless copper shapes (teardrops, artwork), in the pictures only: 1 on BOTTOM

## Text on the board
Ref Des/Silkscreen Bottom: USB TO I2C | ADC | ELECTRONIC LOADS
Ref Des/Silkscreen Top: VUSB | IN | SLIDE | PUSH | LOGIC | nIRQ | VLOGIC | 3.3V | ON | OFF | nEN | 1.8V | SBB3 | SCL | SDA | GND | SPARE INDUCTORS | GUI | OUTPUT SENSE | POWER | MAX77655_EVKIT_D
User.8: NOTES: | SURFACE FINISH: | TESTING: | SOLDERMASK: | MISCELLANEOUS: | SILKSCREEN: | MATERIAL: | TOOLING: | 16.  VENDOR LOGO & DATE CODE REQUIREMENT.  DATE CODE FORMAT MUST BE YYWW ONLY | 17.  FINAL ELECTRICAL TEST TO BE PERFORMED USING PROVIDED IPC-D-356A NETLIST OR ODB++ FORMAT FILE. | 18.  A TIME DOMAIN REFLECTOMETER REPORT FOR EACH IMPEDANCE CONTROLLED LAYER AND A CERTIFICATE | 19. IF PRESENT, ALL BLIND/BURIED VIAS WITH AN ASPECT RATIO <1:1 TO BE PLATED SHUT WITH COPPER WHEN | 20.  FOR ALL DRILL INFORMATION REFER TO DRILL CHART. | 21.  FINISHED SURFACE CONTACTS AND FILLED VIAS TO BE FREE OF ANY PITS. SCRATCHES PROBE MARKS | 23.  PEMNUT | 14.  SOLDERMASK OVER BARE COPPER OR BARE GOLD (BOTH SIDES) WITH LIQUID PHOTO IMAGEABLE (LPI) INK | 13.  DRILL SIZES ARE FINISHED HOLE SIZES. ALL HOLES SHALL BE LOCATED WITHIN .005 DTP,UNLESS SPECIFIED. | 22.  THIEVING: | 9.  ALL TRACES FILLETED OPTION TO ENHANCE RELIABILITY AT PAD JUNCTIONS | 10.  LAYER TO LAYER REGISTRATIONS SHALL BE WITHIN .003 INCHES. | 15. APPLY SILKSCREEN USING A NON-CONDUCTIVE EPOXY INK | 11.  FINISHED COPPER WEIGHT/THICKNESS: | 12. USE CHECKED ITEMS FOR PLATING | 3.  THE PCB SHALL BE FABRICATED TO IPC-6012, TYPE X, CLASS 2. | 4.  BOARD MATERIAL & CONSTRUCTION SHALL MEET THE REQUIREMENTS OF UL796 | 5.  OVERALL BOARD THICKNESS REFER TO LAMINATION DIAGRAM. TOLERANCE APPLIES | 6.  BOW & TWIST NOT TO EXCEED 0.0075 IN. (0.75%) PER LINEAR INCH. | 7.  PHOTO ETCH CIRCUITRY PER ENCLOSED GERBER RS274X OR ODB++ FORMAT FILE. | 8.  IMPEDANCE REQUIREMENTS: IF NO STACKUP IS DEFINED, THE VENDOR IS ALLOWED TO ADJUST THE DIELECTRIC | 1.  DIMENSIONS ARE IN INCHES (EXCEPT WHERE NOTED). | 2.  BOARD MATERIAL: | (x)  FINISH CONDUCTOR SURFACES: IMMERSION GOLD, 2-5 MICRO INCHES OVER | (X)  WHITE | ( )  OTHER ________________________ | ( )  FINGERS TO BE GOLD PLATED. | (X)  REFER TO LAMINATION DIAGRAM FOR FINISHED COPPER WEIGHT/THICKNESS REQUIREMENTS. | (X)  PLACE ON BOTTOM LEGEND LAYER. IF NO BOTTOM LEGEND SUPPLIED, CREATE BOTTOM LEGEND LAYER TO ADD. | ( )  PLACE ON TOP LEGEND LAYER. IF NO TOP LEGEND SUPPLIED,CREATE TOP LEGEND LAYER TO ADD. | ( )  ELECTRODEPOSITED HARD GOLD PLATE, TYPE 1 (99.7% MIN GOLD), GRADE C | (x)  CUSTOM MAXIM TEAL SOLDER MASK. PANTONE #326C. | ( )  OTHER _GREEN__________________ | MINIMUM BARREL PLATING OF .001 IN. PLATED HOLES SHALL NOT BE ROUGH OR IRREGULAR SO AS TO | HINDER PROPER SOLDER WICKING. BARREL RELIEF ON SOLDERMASK ALLOWED ON UNFILLED VIA IN PAD HOLES. | USED AS VIA-IN PAD OR AS A STACKED VIA. BLIND/BURIED VIAS WITH AN ASPECT RATIO >1:1 TO BE FILLED | WITH NON-CONDUCTIVE EPOXY. UNLESS OTHERWISE SPECIFIED. | ( )  NON-CONDUCTIVE EPOXY. FILL AND CAP ALL 0.XXXX INCH DRILLED VIAS. | (x)  SILVER. FILL AND CAP ALL 0.005  INCH DRILLED VIAS. | (REQUIRED UNLESS OTHERWISE SPECIFIED IN QUOTE) | THE PCB SHALL HAVE A VERIFICATION STAMP. | OR OTHER DEFORMITIES THAT COULD EFFECT THE APPERANCE AND PERFORMACE OF THE CONTACT | SURFACE. CONTACTS ARE TO BE AS FLAT AS POSSIBLE. NOT TO EXCEED +/- 0.001" OF FLATNESS. | OF COMPLIANCE SHALL BE PROVIDED BY VENDOR AT TIME OF SHIPMENT. INSTANCES WHERE TDR TESTING | CAN'T BE PERFORMED BECAUSE THE TRACE LENGTH IS TOO SHORT ON THE OUTER LAYERS AT THE PIN ESCAPES | IS ACCEPTABLE, ALL OTHER INSTANCES MUST BE REPORTED. | ( )  SUPPLIER MAY ADD THIEVING TO COMPENSATE FOR LOW COPPER DENSITY AREAS ON THIS DESIGN. | WHERE SPACING PERMITS. | LEGEND TO LEGEND +/- 0.007 INCHES | (X)  SUPPLIER MAY NOT ADD THIEVING TO COMPENSATE FOR LOW COPPER DENSITY AREAS ON THIS DESIGN. | ( )  PEMNUTS TO BE INSTALLED BY FABRICATOR.. | ( )  PEMNUTS NOT TO BE INSTALLED BY FABRICATOR. | (X)  NOT APPLICABLE. | ( )  FILLETED | (X)  NOT FILLETED | (X)  ISOLA 370HR OR EQUIVALENT | ( )  NELCO-4000-13 | ( )  MEGTRON 6 | ( )  ROGERS 4350B | ( )  ROGERS 4003C | ( )  ISOLA-FR408HR OR EQUIVALENT | WORKMANSHIP SHALL CONFORM TO IPC-A-600, CLASS 2, CURRENT REVISIONS. | WITH FLAMMABILITY RATING OF 94V-O. | AFTER ALL LAMINATION AND PLATING PROCESSES. IT IS TO BE MEASURED FROM | TOP PCB METAL TO BOTTOM PCB METAL UNLESS OTHERWISE SPECIFIED. | BOW & TWIST SHOULD BE MEASURED PER IPC-TM-650, METHOD 2.4.22. | DRILL LOCATION AND SIZE CONTROLLED BY EXCELLON CNC DRILL FILE. | THICKNESS AND TRACE WIDTHS TO MEET THE IMPEDANCE REQUIREMENT. IF SPECIFIED, VENDOR MUST FOLLOW AND | MEET THE REQUIREMENTS LISTED IN THE IMPEDANCE TABLE. ANY ADJUSTMENTS MADE TO THE DEFINED STACKUP, | TRACE WIDTH & SPACING THAT IMPACT THE REQUIREMENTS MUST HAVE WRITTEN APPROVAL FROM MAXIM. | UNLESS OTHERWISE SPECIFIED | (USE CHECKED ITEMS FOR MATERIAL) | (KNOOP HARDNESS 130-200), CLASS 1 (50-100 MICRO INCHES THICK) IN ACCORDANCE WITH MIL-G-45204C. | GENERAL SURFACING REQUIREMENTS MUST MEET ANSI/IPC-A-600(CURRENT REV) SECTION 4.0, | CLASS 3 (50-100 MICROINCHES THICK) OVER ELECTRODEPOSITED NICKEL PLATE | IN ACCORDANCE WITH ANSI/IPC-A-600D, SECTION 4.0, CLASS 3 (200-600 MICROINCHES THICK). | 118-236 MICRO INCHES MINIMUM OF ELECTROLESS NICKEL. | THE STARTING COPPER WEIGHT/THICKNESS CAN VARY AS LONG AS THE FINISHED COPPER | WEIGHT/THICKNESS IS NOT LESS THAN THE SPECIFIED VALUE, UNLESS OTHERWISE SPECIFIED. | UNLESS OTHERWISE SPECIFIED: | NOT TO SCALE | TEMPLATE REV 1.7 | TOLERANCES UNLESS OTHERWISE SPECIFIED | FINISH: | +/- | FRACTIONS | SEE NOTES | .XXX +/- .005 | .XX +/- .01 | DECIMALS | ANGLES | THE INFORMATION CONTAINED IN THIS DOCUMENT | IS PROPRIETARY TO MAXIM. THE INFORMATION IN | THIS DOCUMENT IS NOT TO BE SHOWN, REPRODUCED, | OR DISCLOSED TO ANYONE OUTSIDE OF MAXIM | WITHOUT PRIOR WRITTEN PERMISSION FROM MAXIM. | DRAWN BY: | CHECKED BY: DEREK | APPR. BY: | LAKSHMI BHUJ | DATE: | DATE:05/14/2020 | 05/14/2020 | SIZE | E | DRAWING NO. | SHEET 1 OF 1 | REV | D | DESCRIPTION | REVISIONS | APPROVED | DATE | TITLE: | A | RELEASE | MAX77655 EVALUATION BOARD | FABRICATION DWG. | XX-XXXXXX-XX
User.32: FIGURE | SIZE | 5.0 | 8.0 | 32.0 | 37.4 | 39.37 | 45.28 | 62.99 | 35.43 | 196.85 | 47.24x19.69 | TOLERANCE | +3.0/-3.0 | +3.0/-6.0 | PLATED | NON-PLATED | ALL UNITS ARE IN MILS | QTY | 12 | 357 | 3 | 2 | 34 | 36 | 11 | 4 | NOTES | DRILL CHART: TOP to BOTTOM
User.35: FIGURE | SIZE | 5.0 | TOLERANCE | +3.0/-5.0 | PLATED | ALL UNITS ARE IN MILS | QTY | 33 | NOTES | DRILL CHART: TOP to INTERNAL2
